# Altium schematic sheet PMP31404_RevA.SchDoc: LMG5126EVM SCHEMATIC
size 431 x 279 mm; Date: Not shown in title block; ApprovedBy: Not shown in title block; CheckedBy: Not shown in title block; Author: Not shown in title block; CompanyName: Not shown in title block; DrawnBy: F. Mueller; Engineer: Not shown in title block; Organization: Not shown in title block; Address1: Not shown in title block; Address2: Not shown in title block; Address3: Not shown in title block; Address4: Not shown in title block; DocumentNumber: 1; Revision: Use project parameter SCH_Rev; SheetNumber: 1; SheetTotal: 1; PageSetup: Record=PageOptions¦CenterHorizontal=True¦CenterVertical=True¦PrintScale=1.00¦XCorrection=1.00¦YCorrection=1.00¦PrintKind=0¦BorderSize=5000000¦LeftOffset=0¦BottomOffset=0¦Orientation=2¦PaperLength=1000¦PaperWidth=1000¦Scale=100¦PaperSource=15¦PrintQuality=600¦MediaType=1¦DitherType=10¦PaperKind=Letter¦PrintScaleMode=1
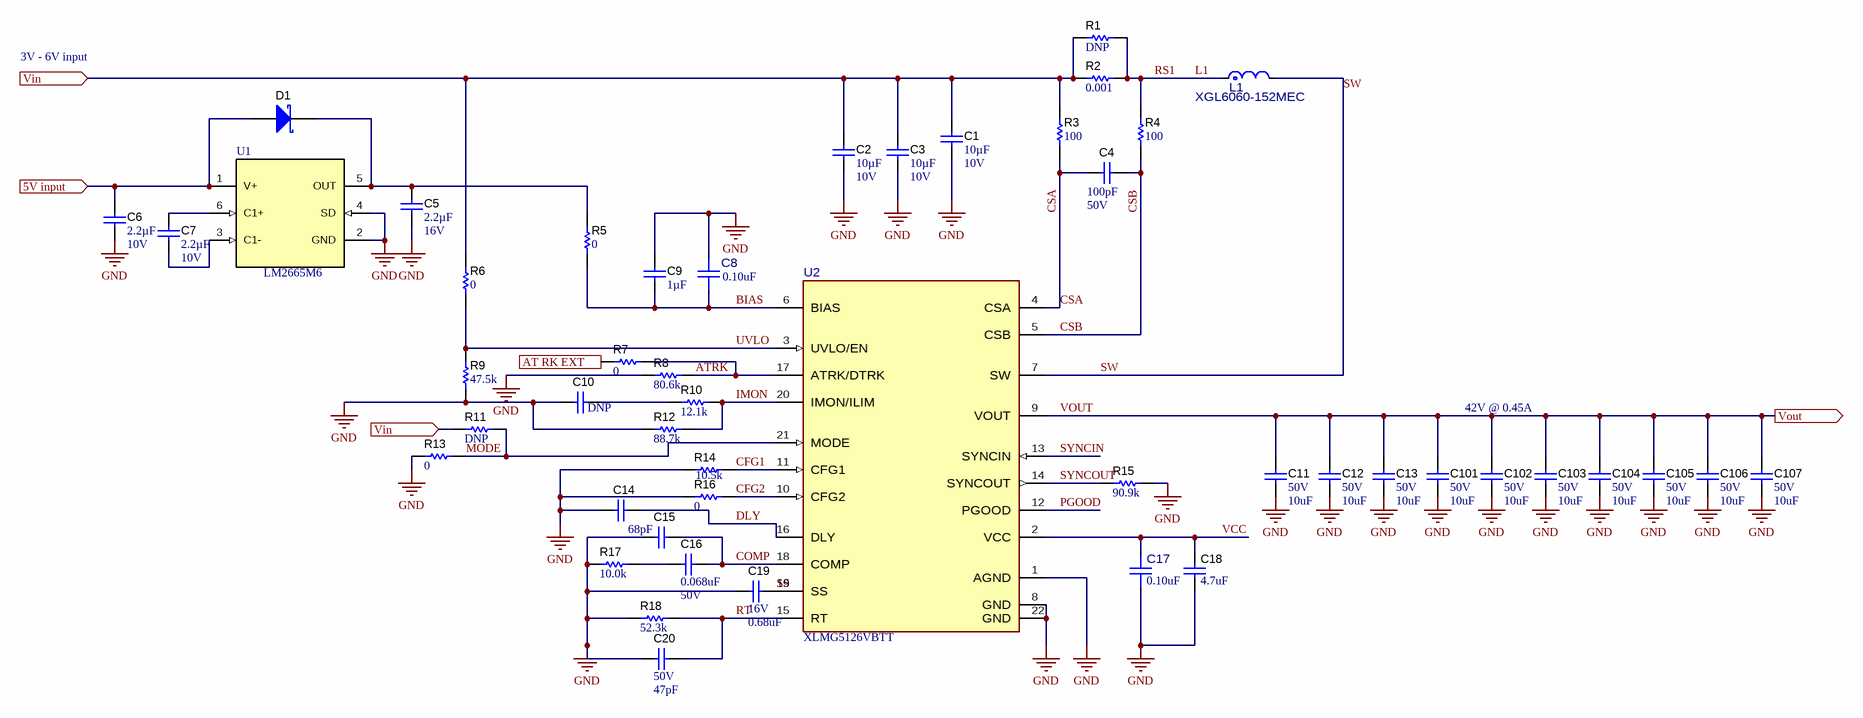
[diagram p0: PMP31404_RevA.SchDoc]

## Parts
C1  Cap_F: 10µF  VDC_V: 10V  [0805_HV]  (hidden comment: GCM21BR71A106KE22L)
C2  Cap_F: 10µF  VDC_V: 10V  [0805_HV]  (hidden comment: GCM21BR71A106KE22L)
C3  Cap_F: 10µF  VDC_V: 10V  [0805_HV]  (hidden comment: GCM21BR71A106KE22L)
C4  VDC_V: 50V  ValueDisplayed: 100pF  [0402S]  (hidden comment: CGA2B2C0G1H101J050BA)
C5  Cap_F: 2.2µF  VDC_V: 16V  [0603]  (hidden comment: EMK107BB7225MA-T)
C6  Cap_F: 2.2µF  VDC_V: 10V  [0603]  (hidden comment: GRM188R71A225KE15J)
C7  Cap_F: 2.2µF  VDC_V: 10V  [0603]  (hidden comment: GRM188R71A225KE15J)
C8  ValueDisplayed: 0.10uF  [FP-GRM155R62A104ME14D_0402-S]  (hidden comment: GRM155R62A104ME14D)
C9  ValueDisplayed: 1µF  [0402]  (hidden comment: CC0402MRX5R6BB105)
C10  (no value)  [0402S]
C11  VDC_V: 50V  ValueDisplayed: 10uF  [1206_180]  (hidden comment: CL31B106KBHNNNE)
C12  VDC_V: 50V  ValueDisplayed: 10uF  [1206_180]  (hidden comment: CL31B106KBHNNNE)
C13  VDC_V: 50V  ValueDisplayed: 10uF  [1206_180]  (hidden comment: CL31B106KBHNNNE)
C14  GRM155R61A334KE15D  [0402S]  (value not drawn)
C15  ValueDisplayed: 68pF  [0402S]  (hidden comment: GRM1555C1H680JA01D)
C16  ValueDisplayed: 0.068uF  VDC_V: 50V  [0402]  (hidden comment: C1005X7R1H683K050BB)
C17  ValueDisplayed: 0.10uF  [FP-GRM155R62A104ME14D_0402-S]  (hidden comment: GRM155R62A104ME14D)
C18  ValueDisplayed: 4.7uF  [0402_065S]  (hidden comment: GRM155R60J475ME87D)
C19  VDC_V: 16V  ValueDisplayed: 0.68uF  [0402]  (hidden comment: C1005X5R1A684K050BB)
C20  VDC_V: 50V  ValueDisplayed: 47pF  [0402S]  (hidden comment: GRM1555C1H470JA01D)
C101  VDC_V: 50V  ValueDisplayed: 10uF  [1206_180]  (hidden comment: CL31B106KBHNNNE)
C102  VDC_V: 50V  ValueDisplayed: 10uF  [1206_180]  (hidden comment: CL31B106KBHNNNE)
C103  VDC_V: 50V  ValueDisplayed: 10uF  [1206_180]  (hidden comment: CL31B106KBHNNNE)
C104  VDC_V: 50V  ValueDisplayed: 10uF  [1206_180]  (hidden comment: CL31B106KBHNNNE)
C105  VDC_V: 50V  ValueDisplayed: 10uF  [1206_180]  (hidden comment: CL31B106KBHNNNE)
C106  VDC_V: 50V  ValueDisplayed: 10uF  [1206_180]  (hidden comment: CL31B106KBHNNNE)
C107  VDC_V: 50V  ValueDisplayed: 10uF  [1206_180]  (hidden comment: CL31B106KBHNNNE)
D1  MBR0520LT1G  [SOD-123]  (value not drawn)
L1  XGL6060-152MEC  [FP-XGL6060-152MEC_SMT_IND_6MM51_6MM71-MFG]
R1  WSLP12061L000FEA  [WSLP1206-001]  (value not drawn)
R2  ValueDisplayed: 0.001  [WSLP1206-001]  (hidden comment: WSLP12061L000FEA)
R3  ValueDisplayed: 100  [0402S]  (hidden comment: ERJ-2RKF1000X)
R4  ValueDisplayed: 100  [0402S]  (hidden comment: ERJ-2RKF1000X)
R5  ValueDisplayed: 0  [0402S]  (hidden comment: CRCW040210K5FKED)
R6  ValueDisplayed: 0  [0402S]  (hidden comment: CRCW040210K5FKED)
R7  ValueDisplayed: 0  [0402S]  (hidden comment: CRCW040210K5FKED)
R8  ValueDisplayed: 80.6k  [0402S]  (hidden comment: CRCW040280K6FKED)
R9  ValueDisplayed: 47.5k  [0402S]  (hidden comment: CRCW040247K5FKED)
R10  ValueDisplayed: 12.1k  [0402S]  (hidden comment: CRCW040212K1FKED)
R11  DNP  [0402S]
R12  ValueDisplayed: 88.7k  [0402S]  (hidden comment: CRCW040288K7FKED)
R13  ValueDisplayed: 0  [0402S]  (hidden comment: CRCW040210K5FKED)
R14  ValueDisplayed: 10.5k  [0402S]  (hidden comment: CRCW040210K5FKED)
R15  ValueDisplayed: 90.9k  [0402S]  (hidden comment: CRCW040290K9FKED)
R16  ValueDisplayed: 0  [0402S]  (hidden comment: CRCW040210K5FKED)
R17  ValueDisplayed: 10.0k  [0402]  (hidden comment: CRCW040210K0FKED)
R18  ValueDisplayed: 52.3k  [0402S]  (hidden comment: CRCW040252K3FKED)
U1  LM2665M6  [DBV0006A_N]
U2  XLMG5126VBTT  [VBT0022A-MFG]

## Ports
5V input (in), AT RK EXT, Vin (in), Vout (out)

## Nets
GND: C1.2 C2.2 C3.2 C5.2 C6.2 C8.2 C9.1 C10.2 C11.2 C12.2 C13.2 C14.2 C15.2 C17.1 C18.2 C19.2 C20.2 C101.2 C102.2 C103.2 C104.2 C105.2 C106.2 C107.2 R8.1 R9.1 R12.1 R13.2 R14.1 R15.2 R16.1 R17.1 R18.1 U1.2(GND) U1.4(SD) U2.1(AGND) U2.8(GND) U2.22(GND)
5V input: C6.1 D1.2(A) U1.1(V+) ; port 5V input
AT RK EXT: R7.1 ; port AT RK EXT
ATRK: R7.2 R8.2 U2.17(ATRK/DTRK)
BIAS: C8.1 C9.2 R5.1 U2.6(BIAS)
CFG1: R14.2 U2.11(CFG1)
CFG2: R16.2 U2.10(CFG2)
COMP: C15.1 C16.1 U2.18(COMP)
CSA: C4.2 R3.1 U2.4(CSA)
CSB: C4.1 R4.1 U2.5(CSB)
DLY: C14.1 U2.16(DLY)
IMON: R10.2 R12.2 U2.20(IMON/ILIM)
L1: L1.1 R1.2 R2.2 R4.2  [also labelled RS1]
MODE: R11.1 R13.1 U2.21(MODE)
PGOOD: U2.12(PGOOD)
RT: C20.1 R18.2 U2.15(RT)
SS: C19.1 U2.19(SS)
SW: L1.2 U2.7(SW)
SYNCIN: U2.13(SYNCIN)
SYNCOUT: R15.1 U2.14(SYNCOUT)
UVLO: R6.1 R9.2 U2.3(UVLO/EN)
VCC: C17.2 C18.1 U2.2(VCC)
Vin: C1.1 C2.1 C3.1 R1.1 R2.1 R3.2 R6.2 R11.2 ; port Vin
VOUT: C11.1 C12.1 C13.1 C101.1 C102.1 C103.1 C104.1 C105.1 C106.1 C107.1 U2.9(VOUT) ; port Vout
NetC5_1: C5.1 D1.1(K) R5.2 U1.5(OUT)
NetC7_1: C7.1 U1.6(C1+)
NetC7_2: C7.2 U1.3(C1-)
NetC10_1: C10.1 R10.1
NetC16_2: C16.2 R17.2

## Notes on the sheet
- 3V - 6V input
- 42V @ 0.45A

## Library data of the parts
C1-C3 = CMP-0008017-1: CAP, CERM, 10 uF, 10 V, +/- 10%, X7R, 0805; Manufacturer: MuRata; TaMin_C: -55°C; Polarized: N; SizeAreaWB_mm2: 6.75; Value1: Unknown; U/M: EA; Value: 10uF; TaMax_C: 125°C; SizeZ_mm: 1.45; SizeX_mm: 2; SizeY_mm: 1.25; Cap_Case: 0805; SizeArea_mm2: 2.5; AEC Category: Q200
C4 = CMP-0006308-2: CAP, CERM, 100 pF, 50 V, +/- 5%, C0G/NP0, AEC-Q200 Grade 1, 0402; Manufacturer: TDK; TaMin_C: -55°C; Polarized: N; SizeAreaWB_mm2: 3; Value1: Unknown; U/M: EA; Value: 100pF; TaMax_C: 125°C; SizeZ_mm: 0.6; SizeX_mm: 1; SizeY_mm: 0.5; Cap_Case: 0402; AEC Qualified: Y; AEC Category: Q200
C5 = CMP-0064934-2: CAP, CERM, 2.2 uF, 16 V,+/- 10%, X7R, 0603; Manufacturer: Taiyo Yuden; TaMin_C: -55°C; Polarized: N; SizeAreaWB_mm2: 4.68; Value1: Unknown; U/M: EA; Value: 2.2uF; TaMax_C: 125°C; SizeZ_mm: 1; SizeX_mm: 1.6; SizeY_mm: 0.8; SizeArea_mm2: 1.28; AEC Category: Q200
C6 C7 = CMP-0084284-1: CAP, CERM, 2.2 µF, 10 V,+/- 10%, X7R, AEC-Q200 Grade 1, 0603; Manufacturer: MuRata; SizeAreaWB_mm2: 4.68; Polarized: N; AEC Qualified: Y; SizeX_mm: 1.6; SizeZ_mm: 1; SizeY_mm: 0.8; U/M: EA; TaMin_C: -55°C; Value: 2.2uF; AEC Category: Q200; TaMax_C: 125°C; SizeArea_mm2: 1.28
C8 C17 = CMP-0093748-2: Chip Multilayer Ceramic Capacitors for General Purpose, 0402, 0.10uF, X5R, 15%, 20%, 100V; Manufacturer: Murata; AEC Qualified: No; Cap_F: 100nF; SizeZ_mm: 0.55mm; Value: 100nF
C9 = CMP-0081457-1: CAP, CERM, 1 µF, 10 V,+/- 20%, X5R, 0402; Manufacturer: Yageo America; TaMin_C: -55°C; Polarized: N; SizeAreaWB_mm2: 3; U/M: EA; Value: 1uF; TaMax_C: 85°C; SizeZ_mm: 0.6; SizeX_mm: 1; SizeY_mm: 0.5; Value2: 10V; AEC Category: Q200
C10 = CMP-0006468-2: DNP; Manufacturer: MuRata; TaMin_C: -55°C; Polarized: N; TempCo: C0G/NP0; SizeAreaWB_mm2: 3; Value1: Unknown; U/M: EA; TaMax_C: 125°C; Tolerance_%: 5%; SizeZ_mm: 0.6; SizeX_mm: 1; SizeY_mm: 0.5; Cap_Case: 0402; Value2: 50V; AEC Category: Q200
C11-C13 C101-C107 = CMP-0008802-2: CAP, CERM, 10 uF, 50 V, +/- 10%, X7R, 1206; Manufacturer: Samsung; TaMin_C: -55°C; Polarized: N; SizeAreaWB_mm2: 10.92; Value1: Unknown; U/M: EA; Value: 10uF; TaMax_C: 125°C; SizeZ_mm: 1.8; SizeX_mm: 3.2; SizeY_mm: 1.6; Cap_Case: 1206; SizeArea_mm2: 5.12; Cap_F: 10µF; AEC Category: Q200
C14 = CMP-0006575-1: CAP, CERM, 0.33 uF, 10 V, +/- 10%, X5R, 0402; Manufacturer: MuRata; TaMin_C: -55°C; Polarized: N; SizeAreaWB_mm2: 3; Value1: Unknown; U/M: EA; Value: 0.33uF; TaMax_C: 85°C; SizeZ_mm: 0.6; SizeX_mm: 1; SizeY_mm: 0.5; Cap_Case: 0402; Value2: 10V; Cap_F: 330nF; AEC Category: Q200
C15 = CMP-0006485-2: CAP, CERM, 68 pF, 50 V, +/- 5%, C0G/NP0, 0402; Manufacturer: MuRata; TaMin_C: -55°C; Polarized: N; SizeAreaWB_mm2: 3; Value1: Unknown; U/M: EA; Value: 68pF; TaMax_C: 125°C; SizeZ_mm: 0.6; SizeX_mm: 1; SizeY_mm: 0.5; Cap_Case: 0402; Value2: 50V; AEC Category: Q200
C16 = CMP-0006299-3: CAP, CERM, 0.068 uF, 50 V, +/- 10%, X7R, 0402; Manufacturer: TDK; TaMax_C: 125°C; SizeZ_mm: 0.6; SizeArea_mm2: 0.5; SizeX_mm: 1; AEC Category: Q200; MFG_Status: TI_Obsolete; ESR_ohm: 56.06m; AEC Qualified: N; SizeAreaWB_mm2: 3; Cap_F: 68nF; TaMin_C: -55°C; U/M: EA; IRMS_A: 684.724mA; Value1: 0.05606 ohm
C18 = CMP-0006553-3: CAP, CERM, 4.7 uF, 6.3 V, +/- 20%, X5R, 0402; Manufacturer: MuRata; TaMin_C: -55°C; ESR_ohm: 9m; Polarized: N; SizeAreaWB_mm2: 3; Value1: 0.009 ohm; U/M: EA; Value: 4.7uF; TaMax_C: 85°C; SizeZ_mm: 0.6; SizeX_mm: 1; SizeY_mm: 0.5; Cap_Case: 0402; Cap_F: 4.7µF; VDC_V: 6.3V; IRMS_A: 1.22A; AEC Category: Q200; Green_Lifecycle: Active; Green_REACh: Incomplete
C19 = CMP-0006271-1: CAP, CERM, 0.68 uF, 10 V, +/- 10%, X7R, 0402; Manufacturer: TDK; TaMin_C: -55°C; Polarized: N; SizeAreaWB_mm2: 3; Value1: Unknown; U/M: EA; Value: 0.68uF; TaMax_C: 85°C; SizeZ_mm: 0.6; SizeX_mm: 1; SizeY_mm: 0.5; Cap_F: 680nF; AEC Category: Q200
C20 = CMP-0006468-2: CAP, CERM, 47 pF, 50 V, +/- 5%, C0G/NP0, 0402; Manufacturer: MuRata; TaMin_C: -55°C; Polarized: N; SizeAreaWB_mm2: 3; Value1: Unknown; U/M: EA; Value: 47pF; TaMax_C: 125°C; SizeZ_mm: 0.6; SizeX_mm: 1; SizeY_mm: 0.5; Cap_Case: 0402; AEC Category: Q200
D1 = CMP-0028524-1: Diode, Schottky, 20 V, 0.5 A, SOD-123; Manufacturer: ON Semiconductor; Io_A: 500mA; Green_Lifecycle: Active; SizeAreaWB_mm2: 13.095; Vr_V: 20V; Green_REACh: Passed; Value1: 0.5A; TJmax_C: 125°C; U/M: EA; Value: 20V; SizeZ_mm: 1.35; SizeX_mm: 3.85; SizeY_mm: 1.7; Vf_V: 385mV; Value2: 0.385V; SizeArea_mm2: 6.545; AEC Category: Q101; RJC_CperW: 150
L1 = CMP-0121324-1: 1.5 µH Shielded Molded Inductor 20.2 A 3.8mOhm Max Nonstandard; Manufacturer: Coilcraft; AEC Grade: Grade 1; AEC Qualified: Yes; DCR_ohm: 3.8m; Ind_H: 1.5µH; Irms: 26A; Isat: 8.9A; Material: Composite; SizeZ_mm: 6.1mm; Value: 1.5uH; Self Resonant Frequency: 41MHz; Shrouded: true; TaMax_C: +125°C; TaMin_C: -40°C; Test Frequency: 1MHz; Tolerance_%: 20%
R1 = CMP-0018569-2: DNP; Manufacturer: Vishay-Dale; Power_W: 1W; TempCo: 275 ppm/C; Value_Code: 1L000; Value1: 1%; U/M: EA; EIA_Code: E96; SizeX_mm: 3.2; SizeY_mm: 1.6; SizeZ_mm: 0.89; SizeArea_mm2: 5.12; AEC Qualified: N; AEC Category: Q200
R2 = CMP-0018569-2: RES, 0.001, 1%, 1 W, 1206; Manufacturer: Vishay-Dale; Power_W: 1W; TempCo: 275 ppm/C; Value_Code: 1L000; U/M: EA; Value: 0.001; EIA_Code: E96; Res_ohm: 1m; SizeX_mm: 3.2; SizeY_mm: 1.6; SizeZ_mm: 0.89; SizeArea_mm2: 5.12; AEC Qualified: N; AEC Category: Q200
R3 R4 = CMP-0026656-1: RES, 100, 1%, 0.1 W, 0402; Manufacturer: Panasonic; Power_W: 100mW; TempCo: 100 ppm/C; Value_Code: 100R; U/M: EA; Value: 100; EIA_Code: E96; SizeX_mm: 1; SizeY_mm: 0.5; SizeZ_mm: 0.6; Value2: 0.1W; VDC_V: 50V; AEC Category: Q200
R5 R6 = CMP-0025960-2: RES,; Manufacturer: Vishay-Dale; Power_W: 63mW; TempCo: 100 ppm/C; Value1: 1%; U/M: EA; Value: 0; EIA_Code: E96; SizeX_mm: 1; SizeY_mm: 0.5; SizeZ_mm: 0.6; VDC_V: 50V; AEC Category: Q200
R7 R13 R16 = CMP-0025960-2: RES,; Manufacturer: Vishay-Dale; Power_W: 63mW; TempCo: 100 ppm/C; Value_Code: 10k5; Value1: 1%; U/M: EA; Value: 0; EIA_Code: E96; SizeX_mm: 1; SizeY_mm: 0.5; SizeZ_mm: 0.6; Value2: 0.063W; VDC_V: 50V; AEC Category: Q200
R8 = CMP-0026570-2: RES, 80.6 k, 1%, 0.063 W, AEC-Q200 Grade 0, 0402; Manufacturer: Vishay-Dale; Power_W: 63mW; TempCo: 100 ppm/C; Value_Code: 80k6; Value: 80.6k; EIA_Code: E96; SizeX_mm: 1; SizeY_mm: 0.5; SizeZ_mm: 0.6; Value2: 0.063W; AEC Qualified: Y; VDC_V: 50V; AEC Category: Q200; AEC Grade: 0
R9 = CMP-0026395-2: RES, 47.5 k, 1%, 0.063 W, AEC-Q200 Grade 0, 0402; Manufacturer: Vishay-Dale; Power_W: 63mW; TempCo: 100 ppm/C; Value_Code: 47k5; Value: 47.5k; EIA_Code: E96; SizeX_mm: 1; SizeY_mm: 0.5; SizeZ_mm: 0.6; Value2: 0.063W; AEC Qualified: Y; VDC_V: 50V; AEC Category: Q200; AEC Grade: 0
R10 = CMP-0025991-2: RES, 12.1 k, 1%, 0.063 W, 0402; Manufacturer: Vishay-Dale; Power_W: 63mW; TempCo: 100 ppm/C; Value_Code: 12k1; U/M: EA; Value: 12.1k; EIA_Code: E96; SizeX_mm: 1; SizeY_mm: 0.5; SizeZ_mm: 0.6; Value2: 0.063W; VDC_V: 50V; AEC Category: Q200
R11 = CMP-0025958-2: Manufacturer: Vishay-Dale; TempCo: 100 ppm/C; Value1: 1%; U/M: EA; EIA_Code: E96; SizeX_mm: 1; SizeY_mm: 0.5; SizeZ_mm: 0.6; VDC_V: 50V; AEC Category: Q200
R12 = CMP-0026586-2: RES, 88.7 k, 1%, 0.063 W, AEC-Q200 Grade 0, 0402; Manufacturer: Vishay-Dale; Power_W: 63mW; TempCo: 100 ppm/C; Value_Code: 88k7; Value: 88.7k; EIA_Code: E96; SizeX_mm: 1; SizeY_mm: 0.5; SizeZ_mm: 0.6; Value2: 0.063W; AEC Qualified: Y; VDC_V: 50V; AEC Category: Q200; AEC Grade: 0
R14 = CMP-0025960-2: RES, 10.5 k, 1%, 0.063 W, 0402; Manufacturer: Vishay-Dale; Power_W: 63mW; TempCo: 100 ppm/C; Value_Code: 10k5; U/M: EA; Value: 10.5k; EIA_Code: E96; SizeX_mm: 1; SizeY_mm: 0.5; SizeZ_mm: 0.6; Value2: 0.063W; VDC_V: 50V; AEC Category: Q200
R15 = CMP-0026605-1: RES, 90.9 k, 1%, 0.063 W, 0402; Manufacturer: Vishay-Dale; Power_W: 63mW; TempCo: 100 ppm/C; Value_Code: 90k9; U/M: EA; Value: 90.9k; EIA_Code: E96; SizeX_mm: 1; SizeY_mm: 0.5; SizeZ_mm: 0.6; Value2: 0.063W; VDC_V: 50V; AEC Category: Q200
R17 = CMP-0025958-2: RES, 10.0 k, 1%, 0.063 W, 0402; Manufacturer: Vishay-Dale; Power_W: 63mW; TempCo: 100 ppm/C; Value_Code: 10k0; U/M: EA; Value: 10.0k; EIA_Code: E96; Res_ohm: 10k; SizeX_mm: 1; SizeY_mm: 0.5; SizeZ_mm: 0.6; Value2: 0.063W; VDC_V: 50V; AEC Category: Q200
R18 = CMP-0026441-1: RES, 52.3 k, 1%, 0.063 W, 0402; Manufacturer: Vishay-Dale; Power_W: 63mW; TempCo: 100 ppm/C; Value_Code: 52k3; U/M: EA; Value: 52.3k; EIA_Code: E96; SizeX_mm: 1; SizeY_mm: 0.5; SizeZ_mm: 0.6; Value2: 0.063W; VDC_V: 50V; AEC Category: Q200
U1 = CMP-0072134-1: Switched Capacitor Voltage Converter, 6-pin SOT-23; Manufacturer: Texas Instruments; PackageTopMarking: S04A*XTT; PowerWise: N; CompType: Switch Caps
U2 = CMP-0125772-1: 2.5MHz 42V wide-VIN synchronous GaN boost converter with output voltage tracking 22-VQFN-FCRLF -40 to 125; Manufacturer: Texas Instruments; SizeZ_mm: 0.85mm; AEC Qualified: No; Max Duty Cycle: 99%; Min Supply Voltage: 2.5V; Number Of Outputs: 1; Output Type: AdjustableProgrammable; Output Voltage: 6-60V; Standoff Height: 0mm; Switching Frequency: 300-2500kHz; TJmax_C: +150°C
